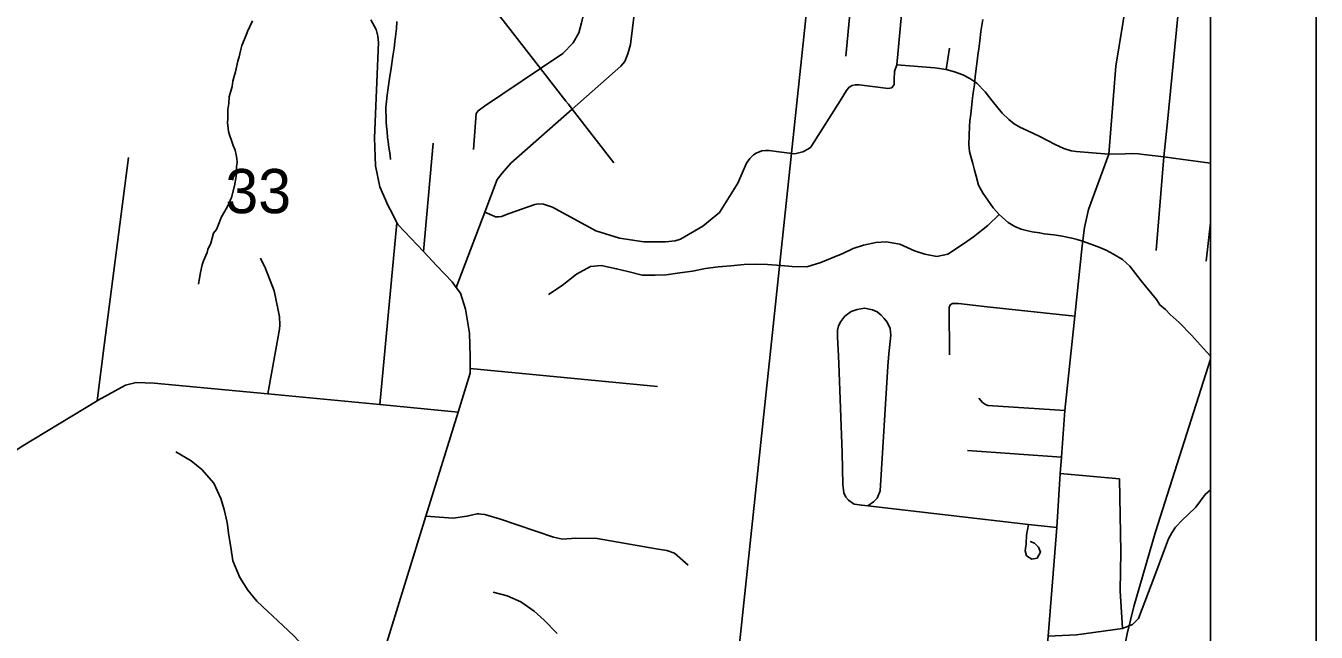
# Model space of a CAD drawing. Extents: x 0 to 34, y -2 to 22.
# Drawn here: x 7.777 to 9, y 19.604 to 20.178 of the extents above; entities that cross this region are included whole.
import ezdxf

# ---------------------------------------------------------------- set-up
doc = ezdxf.new("R2010")
doc.units = 0
for name, color, linetype in [('Default', 7, 'Continuous'), ('GM_X_City_Street', 7, 'Continuous'), ('GM_X_County_Road', 7, 'Continuous'), ('GM_X_Minor_River', 7, 'Continuous'), ('GM_X_Rail_Line', 7, 'Continuous'), ('GM_X_Section', 7, 'Continuous'), ('GM_X_Section_Text', 7, 'Continuous'), ('SH_Cut_Line', 7, 'Continuous'), ('SH_Data', 7, 'Continuous')]:
    doc.layers.add(name, color=color, linetype=linetype)

msp = doc.modelspace()

# ---------------------------------------------------------------- linework, layer by layer
at = {"layer": 'Default'}
msp.add_lwpolyline([(8.9, 19.459), (8.9, 20.4395), (8.5471, 20.4749), (8.4442, 19.5041)], close=True, dxfattribs=at)
at = {"layer": 'GM_X_City_Street'}
for p, q in [((8.6493, 20.1368), (8.6527, 20.157)), ((8.154, 19.9646), (8.1633, 20.0671)), ((8.1129, 19.8197), (8.129, 19.9918)), ((8.8959, 19.9556), (8.9, 19.9917)), ((8.1983, 19.8539), (8.3758, 19.8368)), ((8.6696, 19.7763), (8.7587, 19.7699)), ((8.7575, 19.7546), (8.8135, 19.7494))]:
    msp.add_line(p, q, dxfattribs=at)
for points in [[(8.5543, 20.1494), (8.5633, 20.243), (8.5712, 20.3465), (8.5832, 20.4639)], [(8.598, 20.1195), (8.6002, 20.1228), (8.6002, 20.1274), (8.6005, 20.1351), (8.6026, 20.1415), (8.6116, 20.2369), (8.6222, 20.3449), (8.6359, 20.4668)], [(8.1851, 19.9307), (8.2123, 20.002), (8.224, 20.0328), (8.2287, 20.0388), (8.2369, 20.0482), (8.295, 20.0994), (8.3411, 20.1402), (8.3449, 20.1446), (8.3478, 20.1519), (8.3503, 20.1606), (8.3648, 20.2795), (8.3658, 20.284), (8.3686, 20.2965), (8.378, 20.3146), (8.3913, 20.3434), (8.4292, 20.4263)], [(8.8483, 19.9657), (8.8557, 20.0543), (8.8592, 20.0873), (8.8718, 20.2168), (8.882, 20.3181), (8.8833, 20.3381)], [(8.2014, 20.0611), (8.2042, 20.0952), (8.2058, 20.0979), (8.212, 20.1023), (8.2651, 20.1378), (8.2861, 20.152), (8.2959, 20.1623), (8.3014, 20.1717), (8.304, 20.1811), (8.3061, 20.1902), (8.3099, 20.2478)], [(8.1929, 20.2305), (8.2651, 20.1378), (8.289, 20.1071)], [(8.6026, 20.1415), (8.6385, 20.1386), (8.6493, 20.1368), (8.6572, 20.1346), (8.6653, 20.1318), (8.6717, 20.1283), (8.6783, 20.124), (8.6864, 20.1158), (8.6929, 20.1074), (8.7024, 20.0957), (8.7088, 20.0896), (8.7138, 20.0855), (8.7193, 20.0822), (8.7268, 20.0788), (8.7381, 20.0735), (8.7528, 20.0658), (8.761, 20.0623), (8.7678, 20.0598), (8.7725, 20.0592), (8.8035, 20.0568), (8.8191, 20.0571), (8.8246, 20.0573), (8.8315, 20.0571), (8.8365, 20.0566), (8.8557, 20.0543), (8.8741, 20.0518), (8.8883, 20.0499), (8.9, 20.0484)], [(8.2123, 20.002), (8.2216, 19.9977), (8.2224, 19.9974), (8.2254, 19.9974), (8.2279, 19.9978), (8.2352, 20.0007), (8.2596, 20.0093), (8.2629, 20.0098), (8.268, 20.0096), (8.2763, 20.0067), (8.3175, 19.9843), (8.3398, 19.9774), (8.3628, 19.9739), (8.3833, 19.9738), (8.3925, 19.9748), (8.3978, 19.9762), (8.4189, 19.9887), (8.4347, 20.0017), (8.452, 20.0294), (8.4603, 20.0482), (8.4635, 20.0526), (8.4669, 20.0561), (8.4695, 20.0578), (8.4746, 20.0601), (8.4782, 20.0604), (8.4818, 20.0603), (8.4909, 20.059), (8.506, 20.0572), (8.5137, 20.0589), (8.519, 20.0619), (8.5212, 20.0635), (8.5221, 20.0649), (8.549, 20.1072), (8.5551, 20.117), (8.5576, 20.1201), (8.5603, 20.1217), (8.5632, 20.1225), (8.5669, 20.1225), (8.5871, 20.12), (8.5942, 20.119), (8.598, 20.1195)], [(8.289, 20.1071), (8.2914, 20.104), (8.295, 20.0994), (8.3345, 20.0487)], [(7.8449, 19.8234), (7.8517, 19.8757), (7.8747, 20.0535)], [(8.0067, 19.8298), (8.0176, 19.8911), (8.018, 19.8954), (8.0176, 19.9028), (8.0165, 19.9091), (8.0127, 19.9274), (8.0044, 19.9486), (7.9996, 19.9582)], [(8.5544, 19.732), (8.5525, 19.7361), (8.5515, 19.744), (8.5508, 19.7742), (8.5478, 19.8586), (8.5471, 19.8721), (8.5464, 19.8832), (8.5464, 19.8903), (8.5475, 19.8942), (8.5495, 19.8984), (8.5533, 19.9033), (8.5595, 19.9078), (8.5649, 19.9098), (8.5721, 19.911), (8.5795, 19.9096), (8.5841, 19.9074), (8.5877, 19.9043), (8.5906, 19.9013), (8.5936, 19.8977)], [(8.6524, 19.8667), (8.6521, 19.9117), (8.6531, 19.9141), (8.6553, 19.9155), (8.6611, 19.9154), (8.6881, 19.9124), (8.7712, 19.9033)], [(8.5936, 19.8977), (8.5962, 19.8919), (8.5968, 19.8854), (8.5951, 19.8678), (8.5941, 19.856), (8.587, 19.738), (8.584, 19.7312), (8.5805, 19.7277), (8.5752, 19.724)], [(8.6804, 19.8259), (8.6838, 19.8216), (8.6868, 19.8198), (8.689, 19.8189), (8.7618, 19.8143)], [(8.8165, 19.6079), (8.8144, 19.6434), (8.8149, 19.6804), (8.8135, 19.7494)], [(8.7461, 19.6005), (8.7729, 19.6019), (8.8165, 19.6079), (8.8258, 19.6115), (8.8315, 19.6174), (8.8472, 19.6579), (8.8562, 19.6826), (8.8601, 19.6927), (8.8631, 19.6984), (8.8666, 19.7038), (8.8733, 19.7108), (8.8785, 19.7155), (8.8861, 19.7228), (8.8948, 19.7345), (8.9, 19.739)], [(8.5544, 19.732), (8.5568, 19.7292), (8.5622, 19.7256), (8.5694, 19.7244), (8.5752, 19.724), (8.7273, 19.7064), (8.7541, 19.7033)], [(8.1565, 19.7142), (8.1824, 19.7122), (8.1953, 19.7141), (8.2049, 19.7162), (8.2067, 19.7162), (8.2084, 19.7161), (8.2121, 19.7156), (8.2272, 19.7114), (8.2772, 19.6942), (8.2859, 19.6924), (8.2985, 19.6933), (8.3186, 19.6931), (8.3746, 19.6833), (8.3848, 19.6816), (8.392, 19.6791), (8.405, 19.6678)], [(8.7289, 19.69), (8.733, 19.6887), (8.7368, 19.6848), (8.7387, 19.6799), (8.7357, 19.6744), (8.7305, 19.6733), (8.7256, 19.6766), (8.7242, 19.6813), (8.7253, 19.6878), (8.7256, 19.6961), (8.7273, 19.7064)]]:
    msp.add_lwpolyline(points, dxfattribs=at)
at = {"layer": 'GM_X_County_Road'}
for points in [[(8.8284, 19.1591), (8.8248, 19.1716), (8.7779, 19.3279), (8.7401, 19.4586), (8.7362, 19.4674), (8.7376, 19.4898), (8.7426, 19.5636), (8.7461, 19.6005), (8.7541, 19.7033), (8.7575, 19.7546), (8.7587, 19.7699), (8.7618, 19.8143), (8.7712, 19.9033), (8.7782, 19.97), (8.7806, 19.9874), (8.7841, 20.0044), (8.8035, 20.0568), (8.8102, 20.14), (8.8233, 20.2212)], [(8.1243, 20.0008), (8.1224, 20.0044), (8.1207, 20.0078), (8.1129, 20.0258), (8.1085, 20.0459), (8.1077, 20.0722), (8.1116, 20.1625), (8.1109, 20.1686), (8.1092, 20.1747), (8.1042, 20.1838)], [(8.187, 19.8127), (8.1983, 19.8494), (8.1983, 19.8539), (8.1985, 19.8653), (8.1976, 19.8874), (8.194, 19.9102), (8.1892, 19.9251), (8.1851, 19.9307), (8.1814, 19.9358), (8.1667, 19.9511), (8.154, 19.9646), (8.13, 19.9899), (8.129, 19.9918), (8.1243, 20.0008)], [(7.4347, 19.4382), (7.4921, 19.45), (7.5027, 19.4538), (7.5138, 19.4604), (7.5307, 19.4796), (7.5509, 19.5109), (7.5527, 19.5131), (7.576, 19.5394), (7.6036, 19.5706), (7.625, 19.5923), (7.6537, 19.6303), (7.6656, 19.6552), (7.6964, 19.7157), (7.7085, 19.7337), (7.719, 19.7433), (7.7728, 19.7798), (7.8449, 19.8234), (7.8458, 19.824), (7.8719, 19.8382), (7.8818, 19.8407), (7.8988, 19.84), (8.0067, 19.8298), (8.1129, 19.8197), (8.187, 19.8127)], [(8.1167, 19.5855), (8.1565, 19.7142), (8.187, 19.8127)]]:
    msp.add_lwpolyline(points, dxfattribs=at)
at = {"layer": 'GM_X_Minor_River'}
for points in [[(7.9922, 20.1829), (7.9874, 20.1728), (7.9862, 20.1694), (7.9821, 20.1596), (7.9808, 20.1547), (7.9795, 20.149), (7.9783, 20.1448), (7.9761, 20.1346), (7.9744, 20.1293), (7.9736, 20.1259), (7.9727, 20.121), (7.9701, 20.1112), (7.9696, 20.1047), (7.9687, 20.099), (7.9686, 20.0952), (7.9688, 20.0903), (7.9683, 20.0869), (7.9686, 20.0838), (7.9693, 20.0784), (7.9703, 20.075), (7.9721, 20.0696), (7.9738, 20.065), (7.9756, 20.0607), (7.9766, 20.0562), (7.9773, 20.0527), (7.9776, 20.0489), (7.9771, 20.0451), (7.9769, 20.039), (7.9765, 20.0356), (7.9751, 20.0269), (7.9721, 20.0159), (7.9685, 20.0072), (7.9625, 19.9968), (7.9604, 19.9919), (7.958, 19.9855), (7.9552, 19.9821), (7.9527, 19.9727), (7.9499, 19.9666), (7.949, 19.9636), (7.9458, 19.9557), (7.9445, 19.9519), (7.9428, 19.9447), (7.9415, 19.9375), (7.9411, 19.9337)], [(8.1288, 20.1825), (8.1286, 20.1757), (8.1271, 20.1632), (8.1262, 20.1571), (8.1252, 20.1495), (8.1234, 20.1381), (8.122, 20.1283), (8.1206, 20.1195), (8.1196, 20.1127), (8.1191, 20.1066), (8.1186, 20.1009), (8.1185, 20.0971), (8.1187, 20.0926), (8.1189, 20.0872), (8.1192, 20.083), (8.1198, 20.0781), (8.1201, 20.0727), (8.1207, 20.0689), (8.1213, 20.0632), (8.122, 20.0601), (8.1226, 20.0555), (8.1229, 20.0517)], [(8.9, 19.8656), (8.8931, 19.8729), (8.882, 19.8854), (8.8702, 19.8976), (8.8616, 19.905), (8.8572, 19.9097), (8.852, 19.9141), (8.8487, 19.9191), (8.8443, 19.9246), (8.8384, 19.932), (8.834, 19.937), (8.8288, 19.9437), (8.8233, 19.9507), (8.8166, 19.957), (8.808, 19.9621), (8.8009, 19.9658), (8.7934, 19.969), (8.7787, 19.9744), (8.7734, 19.9761), (8.7685, 19.9773), (8.7576, 19.9795), (8.7515, 19.9805), (8.7424, 19.9815), (8.7379, 19.9824), (8.731, 19.9833), (8.7254, 19.9846), (8.7205, 19.9859), (8.7144, 19.9884), (8.7081, 19.992), (8.6999, 19.9994), (8.694, 20.0061), (8.6889, 20.0131), (8.6845, 20.0197), (8.6801, 20.0274), (8.6777, 20.0359), (8.6763, 20.0416), (8.6746, 20.0481), (8.6729, 20.0546), (8.6715, 20.0593), (8.6709, 20.0657), (8.6714, 20.0833), (8.6719, 20.0882), (8.6728, 20.0946), (8.6734, 20.1007), (8.6739, 20.1072), (8.6749, 20.1148), (8.6762, 20.1223), (8.6768, 20.1299), (8.6778, 20.1379), (8.6788, 20.1447), (8.6793, 20.1504), (8.6802, 20.1565), (8.6812, 20.1641), (8.6822, 20.1728), (8.684, 20.1842)], [(8.6996, 19.9998), (8.6889, 19.9892), (8.6753, 19.9785), (8.6657, 19.9719), (8.651, 19.962), (8.6407, 19.96), (8.6293, 19.9621), (8.6195, 19.9654), (8.6056, 19.9715), (8.5924, 19.9737), (8.5829, 19.9732), (8.571, 19.9708), (8.5614, 19.9676), (8.5514, 19.9629), (8.5415, 19.9586), (8.5307, 19.9543), (8.5173, 19.95), (8.5036, 19.9504), (8.4926, 19.9514), (8.4801, 19.9525), (8.4691, 19.9527), (8.4581, 19.9522), (8.4455, 19.951), (8.4333, 19.9502), (8.4215, 19.9486), (8.4089, 19.9462), (8.3971, 19.9446), (8.3841, 19.9426), (8.3735, 19.9421), (8.3613, 19.9424), (8.3477, 19.9458), (8.3371, 19.9483), (8.3224, 19.9513), (8.3125, 19.9504), (8.299, 19.9432), (8.2855, 19.9325), (8.2727, 19.924)], [(7.9195, 19.7751), (7.9341, 19.7664), (7.9442, 19.7582), (7.9556, 19.7454), (7.9621, 19.7307), (7.9653, 19.7204), (7.968, 19.7082), (7.9696, 19.6959), (7.9717, 19.6849), (7.9736, 19.6719), (7.9801, 19.6561), (7.9878, 19.6442), (7.9962, 19.6337), (8.0066, 19.6239), (8.0208, 19.6106), (8.0312, 19.6009), (8.0438, 19.5873), (8.0511, 19.5776), (8.0573, 19.5656), (8.0605, 19.5553), (8.0606, 19.5439), (8.0598, 19.5291), (8.0607, 19.5184)], [(8.2203, 19.6423), (8.2335, 19.6386), (8.2463, 19.6329), (8.259, 19.6242), (8.2686, 19.6156), (8.2809, 19.6032)]]:
    msp.add_lwpolyline(points, dxfattribs=at)
at = {"layer": 'GM_X_Rail_Line'}
msp.add_line((8.9, 19.8629), (8.8477, 19.6993), dxfattribs=at)
for points in [[(8.9, 16.3574), (8.9, 20.9), (7.5809, 20.9), (7.5548, 20.6102), (7.5526, 20.5853), (7.5512, 20.5718), (7.5261, 20.3339), (7.4466, 19.581), (7.4316, 19.4382), (7.3781, 18.9333), (7.3765, 18.917), (7.3254, 18.3889), (7.2924, 18.0527)], [(8.9, 19.0406), (8.8798, 19.1011), (8.8375, 19.2515), (8.8244, 19.303), (8.8145, 19.3965), (8.8055, 19.4781), (8.8084, 19.5387), (8.8208, 19.6027), (8.8272, 19.6287), (8.8477, 19.6993)]]:
    msp.add_lwpolyline(points, dxfattribs=at)
at = {"layer": 'GM_X_Section'}
msp.add_lwpolyline([(8.5471, 20.4749), (8.4442, 19.5041), (7.4489, 19.5784), (7.556, 20.5828)], close=True, dxfattribs=at)
at = {"layer": 'SH_Cut_Line'}
msp.add_lwpolyline([(6.0485, 14.702), (6.1464, 14.7771), (6.2416, 14.8366), (6.3391, 14.8719), (6.8207, 14.994), (7.0052, 15.0295), (7.018, 15.0319), (7.3068, 15.0956), (7.4995, 15.1593), (7.5948, 15.214), (7.6912, 15.289), (7.9856, 15.5639), (8.2003, 15.8586), (8.2596, 15.9572), (8.5337, 16.2495), (8.6286, 16.3042), (8.7283, 16.3459), (8.827, 16.358), (8.9, 16.3574), (8.9, 20.9), (2.1, 20.9)], dxfattribs=at)
at = {"layer": 'SH_Data'}
for p, q in [((9, 21), (9, 14)), ((8.9, 20.9), (8.9, 14.1))]:
    msp.add_line(p, q, dxfattribs=at)

# ---------------------------------------------------------------- texts
at = {"layer": 'GM_X_Section_Text'}
msp.add_text('33', height=0.04186, rotation=0, dxfattribs=at).set_placement((7.9664, 20.0009))

doc.saveas('drawing.dxf')
